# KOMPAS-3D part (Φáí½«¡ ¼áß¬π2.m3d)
File: created 06.04.2016 12:01:11, last saved 22.07.2016 15:41:29.
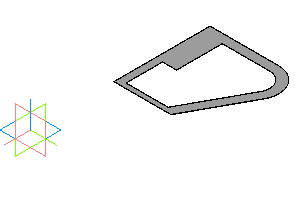
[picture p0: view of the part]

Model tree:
1. Эскиз:1
2. Операция выдавливания:1
     Толщина стенки 2 = 15; Расстояние 1 = 0.6; Расстояние 2 = 96.2519
3. Эскиз:2
4. Операция выдавливания:2
     Толщина стенки 1 = 12; Толщина стенки 2 = 12; Расстояние 1 = 0.6; Расстояние 2 = 0.6
5. Эскиз:3
6. Операция выдавливания:3
     Толщина стенки 1 = 35; Толщина стенки 2 = 35; Расстояние 1 = 0.6; Расстояние 2 = 0.6
7. Эскиз:4
8. Операция выдавливания:4
     Толщина стенки 1 = 15; Толщина стенки 2 = 30; Расстояние 1 = 0.6; Расстояние 2 = 0.6
9. Эскиз:5
10. Вырезать элемент выдавливания:2
     Толщина стенки 2 = 1.5; Расстояние 1 = 112.6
